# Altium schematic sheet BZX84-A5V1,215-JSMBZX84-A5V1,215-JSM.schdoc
size 127 x 101 mm
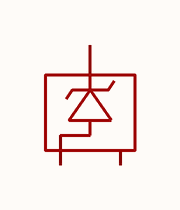
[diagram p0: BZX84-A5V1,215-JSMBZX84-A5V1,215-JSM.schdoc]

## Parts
D?  bzx84-a5v1,215-jsm  [SOT-23-3_L3.0-W1.7-P0.95-LS2.9-BR]  (value not drawn)

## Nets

Not connected (* = marked no-connect by the designer): D? 1 2 3

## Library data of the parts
D? = bzx84-a5v1,215-jsm: 二极管配置:1个独立式;稳压值(标称值):-;稳压值(范围值):4.98V~5.2V;耗散功率(Pd):225mW;; Manufacturer: JSMSEMI(杰盛微); AddInBom: yes; ModelId: 89cb27a44ab2466697082bb9fd73a7d0; ModelName: SOT-23-3L_L2.9-W1.6-H1.1-LS2.8-P0.95; ModelTransform: 114.173,110.236,0,90,0,0,0,0,0; Diode Configuration: 1个独立式; Reverse Leakage Current (Ir): 2uA@1.5V; Pd - Power Dissipation: 225mW; Impedance(Zzt): 80Ω; Impedance(Zzk): 500Ω; Operating Junction Temperature Range: -55℃~+150℃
